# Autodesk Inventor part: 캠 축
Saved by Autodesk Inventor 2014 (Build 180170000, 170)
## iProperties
Created: 2026-06
Part Number: 캠 축
Material: 강철, 탄소
Document SubType Name: Modeling
Designer: dg
Density: 7.87 g/cm^3
Appearance: 반연마
Mass: 268.766 g
Surface Area: 81.6991 cm^2
Volume: 34.1508 cm^3
Author: jhkim
Creation Date: 2026-05-29
Sending System: Autodesk Inventor 2027
Preprocessor: ST-DEVELOPER v20.1
Author: dg
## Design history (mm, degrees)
node "캠 축1"
node "솔리드1"
node "기준1"
